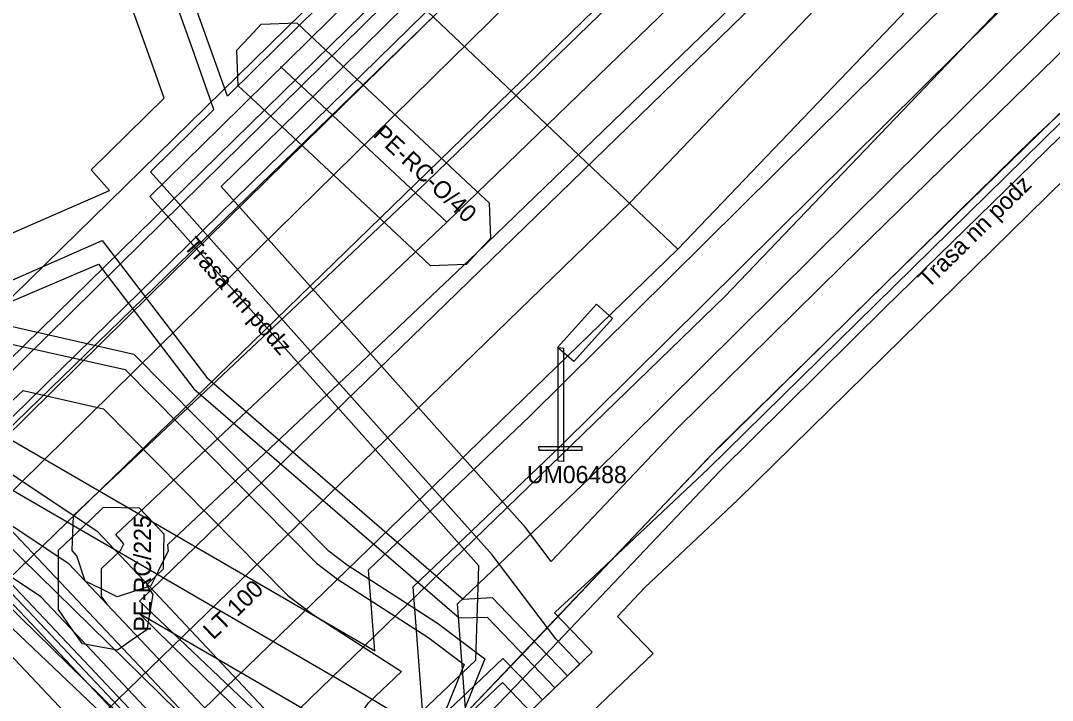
# Model space of a CAD drawing. Extents: x -762993 to -761845, y -975230 to -974501.
# Drawn here: x -762256.7 to -762232.71, y -974983.83 to -974968.01 of the extents above; entities that cross this region are included whole.
import ezdxf

# ---------------------------------------------------------------- set-up
doc = ezdxf.new("R2010")
doc.units = 0
for name, color, linetype in [('IS_CETIN_chranicka', 7, 'Continuous'), ('IS_CETIN_OP', 7, 'Continuous'), ('IS_CETIN_podzem metalika zam', 7, 'Continuous'), ('IS_CETIN_podzem optika zam', 7, 'Continuous'), ('IS_CEZ-D_anotace', 7, 'Continuous'), ('IS_CEZ-D_el vedeni NN podzem', 7, 'Continuous'), ('IS_CEZ-D_el vedeni VN podzem', 7, 'Continuous'), ('IS_CEZ-D_el vedeni VN podzem soubeh investice', 7, 'Continuous'), ('IS_CEZ-D_OP', 7, 'Continuous'), ('IS_CEZ-T_parovod', 7, 'Continuous'), ('IS_CEZ-T_parovod OP', 7, 'Continuous'), ('IS_DPmUL_OP', 7, 'Continuous'), ('IS_DPmUL_trakce vedeni', 7, 'Continuous'), ('IS_DPmUL_VO lampy', 7, 'Continuous'), ('IS_DPmUL_VO lampy anotace', 7, 'Continuous'), ('IS_DPmUL_VO vedeni podzem', 7, 'Continuous'), ('IS_GASNET_plyn NTL anotace', 7, 'Continuous'), ('IS_GASNET_plyn NTL pripojky', 7, 'Continuous'), ('IS_GASNET_plyn NTL rad', 7, 'Continuous'), ('IS_GASNET_plyn OP', 7, 'Continuous'), ('IS_SCVK_vodovod anotace', 7, 'Continuous'), ('IS_SCVK_vodovod OP', 7, 'Continuous'), ('IS_SCVK_vodovod pripojky', 7, 'Continuous'), ('IS_SCVK_vodovod privadec', 7, 'Continuous'), ('IS_T-Mobile_OP', 7, 'Continuous'), ('IS_T-Mobile_podzem optika', 7, 'Continuous'), ('IS_TPS_podzem metalika', 7, 'Continuous')]:
    doc.layers.add(name, color=color, linetype=linetype)

msp = doc.modelspace()

# ---------------------------------------------------------------- linework, layer by layer
at = {"layer": 'IS_CETIN_chranicka'}
for points in [[(-762258.261, -974979.697), (-762251.681, -974986.657)], [(-762258.479, -974979.903), (-762251.899, -974986.863)]]:
    msp.add_lwpolyline(points, dxfattribs=at)
at = {"layer": 'IS_CETIN_OP'}
for p, q in [((-762254.387, -974973.681), (-762261.009, -974980.205)), ((-762252.983, -974975.105), (-762257.358, -974979.415))]:
    msp.add_line(p, q, dxfattribs=at)
for points in [[(-762224.35, -974947.167), (-762239.502, -974961.816), (-762240.717, -974963.012), (-762243.097, -974965.371), (-762252.983, -974975.106)], [(-762241.648, -974961.122), (-762242.123, -974961.588), (-762244.503, -974963.949), (-762254.387, -974973.68)], [(-762281.558, -974973.1), (-762274.643, -974973.209), (-762271.979, -974979.65), (-762261.259, -974982.679), (-762258.547, -974981.068), (-762252.538, -974987.424), (-762250.848, -974989.451)], [(-762257.358, -974979.415), (-762251.042, -974986.096), (-762249.989, -974987.358)]]:
    msp.add_lwpolyline(points, dxfattribs=at)
at = {"layer": 'IS_CETIN_podzem metalika zam'}
for points in [[(-762225.045, -974946.448), (-762240.2, -974961.1), (-762241.42, -974962.3), (-762243.8, -974964.66), (-762253.685, -974974.393)], [(-762253.685, -974974.393), (-762258.26, -974978.9)]]:
    msp.add_lwpolyline(points, dxfattribs=at)
at = {"layer": 'IS_CETIN_podzem optika zam'}
msp.add_lwpolyline([(-762282.79, -974972.08), (-762273.97, -974972.22), (-762271.24, -974978.82), (-762261.4, -974981.6), (-762258.37, -974979.8), (-762251.79, -974986.76), (-762250.08, -974988.81)], dxfattribs=at)
at = {"layer": 'IS_CEZ-D_el vedeni NN podzem'}
for points in [[(-762247.847, -974984.536), (-762246.114, -974982.893), (-762246.05, -974980.697), (-762253.7, -974972.107), (-762252.057, -974970.493), (-762250.973, -974969.428), (-762239.791, -974958.41), (-762235.916, -974954.845), (-762234.541, -974953.31), (-762221.186, -974940.477), (-762220.991, -974940.306), (-762216.22, -974936.128), (-762203.456, -974923.483), (-762203.186, -974923.213), (-762202.673, -974922.708), (-762197.126, -974917.211), (-762182.367, -974902.622)], [(-762292.054, -974954.011), (-762292.145, -974953.937), (-762291.358, -974953.166), (-762290.951, -974953.062), (-762289.257, -974952.627), (-762288.969, -974952.553), (-762288.196, -974955.224), (-762285.856, -974966.323), (-762272.266, -974963.899), (-762272.118, -974964.474), (-762271.031, -974969.629), (-762269.385, -974976.005), (-762268.341, -974977.635), (-762265.074, -974979.234), (-762262.734, -974979.395), (-762260.132, -974977.413), (-762257.177, -974974.654), (-762254.887, -974973.678), (-762252.67, -974976.58), (-762246.502, -974981.906), (-762245.853, -974981.888), (-762245.113, -974982.66), (-762244.276, -974983.534), (-762244.131, -974983.395)], [(-762234.834, -974953.037), (-762236.201, -974954.564), (-762240.067, -974958.12), (-762251.254, -974969.143), (-762251.891, -974969.769), (-762252.332, -974968.535), (-762253.876, -974964.216), (-762253.878, -974964.21), (-762254.236, -974964.12), (-762254.284, -974964.314)], [(-762272.945, -974957.326), (-762271.974, -974963.424), (-762270.341, -974970.221), (-762269.011, -974975.847), (-762268.064, -974977.325), (-762264.969, -974978.841), (-762262.749, -974978.993), (-762260.312, -974977.034), (-762257.295, -974974.217), (-762254.804, -974973.128), (-762252.371, -974976.312), (-762246.411, -974981.474), (-762245.736, -974981.431), (-762244.85, -974982.356), (-762243.987, -974983.257), (-762244.131, -974983.395)], [(-762244.131, -974983.395), (-762243.698, -974982.98), (-762244.256, -974982.397), (-762245.738, -974980.442), (-762253.68, -974971.528), (-762252.205, -974970.078), (-762252.708, -974968.669), (-762254.179, -974964.552), (-762254.181, -974964.546), (-762254.333, -974964.508), (-762254.284, -974964.314)], [(-762223.572, -974968.926), (-762223.717, -974969.063), (-762224.197, -974968.555), (-762227.309, -974965.261), (-762240.713, -974978.438), (-762243.49, -974981.054), (-762244.149, -974981.659), (-762244.288, -974981.787), (-762243.667, -974982.434), (-762243.409, -974982.703), (-762244.131, -974983.395)], [(-762193.524, -974995.955), (-762196.315, -974995.713), (-762196.321, -974995.763), (-762206.82, -974995.223), (-762221.661, -974993.755), (-762245.947, -974992.564), (-762248.224, -974989.473), (-762248.642, -974987.043), (-762248.543, -974986.191), (-762247.498, -974984.757), (-762245.839, -974983.184), (-762245.485, -974982.848), (-762245.111, -974983.239), (-762244.564, -974983.81), (-762244.131, -974983.395)], [(-762193.524, -974995.955), (-762196.714, -974995.678), (-762196.674, -974995.344), (-762206.79, -974994.824), (-762221.625, -974993.357), (-762245.684, -974992.246), (-762247.846, -974989.312), (-762248.238, -974987.032), (-762248.152, -974986.29), (-762247.149, -974984.977), (-762245.644, -974983.55), (-762245.499, -974983.413), (-762245.127, -974983.801), (-762244.853, -974984.087), (-762244.131, -974983.395)]]:
    msp.add_lwpolyline(points, dxfattribs=at)
at = {"layer": 'IS_CEZ-D_el vedeni VN podzem'}
for points in [[(-762178.94, -974917.38), (-762180.88, -974919.33), (-762183.85, -974922.18), (-762189.02, -974927.27), (-762191.6, -974929.28), (-762204.29, -974941.85), (-762215.61, -974952.68), (-762222.04, -974959.06), (-762225.71, -974962.96), (-762226.91, -974964.67), (-762236.89, -974974.42), (-762240.73, -974978.21), (-762245.09, -974982.81)], [(-762269.579, -974969.967), (-762269.216, -974971.463), (-762268.263, -974975.531), (-762267.512, -974976.705), (-762264.757, -974978.053), (-762262.777, -974978.189), (-762259.951, -974977.791), (-762257.059, -974975.091), (-762254.069, -974975.768), (-762249.558, -974980.329), (-762249.105, -974980.676), (-762247.006, -974982.026), (-762245.904, -974982.859), (-762247.37, -974986.49), (-762247.43, -974987.01), (-762247.09, -974988.99), (-762245.16, -974991.61), (-762241.64, -974993.28), (-762221.77, -974994.95), (-762206.91, -974996.42), (-762195.262, -974997.018), (-762195.119, -974995.819), (-762194.458, -974994.436)], [(-762269.605, -974971.556), (-762268.637, -974975.689), (-762267.788, -974977.015), (-762264.863, -974978.447), (-762262.763, -974978.591), (-762259.77, -974978.169), (-762256.941, -974975.528), (-762254.271, -974976.132), (-762249.823, -974980.63), (-762249.335, -974981.004), (-762247.235, -974982.354), (-762246.39, -974982.993), (-762247.761, -974986.39), (-762247.834, -974987.021), (-762247.468, -974989.151), (-762245.422, -974991.928), (-762241.746, -974993.673), (-762221.806, -974995.348), (-762206.94, -974996.819), (-762194.909, -974997.437), (-762194.72, -974995.856), (-762194.458, -974994.436)], [(-762245.09, -974982.81), (-762246.99, -974984.79), (-762247.4, -974985.77), (-762247.54, -974987.01), (-762247.5, -974988.33), (-762246.71, -974990.37), (-762245.42, -974991.69), (-762241.81, -974993.76), (-762241.12, -974993.94), (-762236.96, -974994.44), (-762231.73, -974994.71), (-762227.11, -974994.8), (-762224.15, -974995.55), (-762219.32, -974995.76), (-762207.1, -974996.91), (-762200.67, -974997.34), (-762199.56, -974997.3), (-762198.56, -974996.73), (-762198.04, -974995.71)]]:
    msp.add_lwpolyline(points, dxfattribs=at)
at = {"layer": 'IS_CEZ-D_el vedeni VN podzem soubeh investice'}
msp.add_lwpolyline([(-762246.655, -974985.018), (-762244.801, -974983.086), (-762240.444, -974978.49), (-762236.61, -974974.705), (-762226.604, -974964.93), (-762225.399, -974963.213), (-762221.753, -974959.339), (-762215.331, -974952.967), (-762204.011, -974942.137), (-762191.335, -974929.581), (-762188.756, -974927.571), (-762183.571, -974922.467), (-762180.6, -974919.615), (-762178.658, -974917.664), (-762169.2, -974908.366)], dxfattribs=at)
at = {"layer": 'IS_CEZ-D_OP'}
msp.add_line((-762242.183, -974981.196), (-762242.822, -974981.871), dxfattribs=at)
for points in [[(-762252.034, -974971.872), (-762251.356, -974971.206), (-762250.272, -974970.141), (-762239.101, -974959.134), (-762235.203, -974955.548), (-762233.821, -974954.005), (-762220.51, -974941.214), (-762220.332, -974941.058), (-762215.538, -974936.86), (-762202.751, -974924.192), (-762202.482, -974923.923), (-762201.97, -974923.419), (-762196.423, -974917.922), (-762181.665, -974903.334)], [(-762224.65, -974960.374), (-762226.487, -974962.327), (-762227.675, -974964.02), (-762237.591, -974973.706), (-762241.444, -974977.51), (-762244.368, -974980.594)], [(-762254.633, -974971.962), (-762255.06, -974971.482), (-762253.362, -974969.813), (-762253.65, -974969.005), (-762254.943, -974965.386), (-762255.548, -974965.235), (-762254.96, -974962.907)], [(-762222.885, -974969.653), (-762223.757, -974970.477), (-762224.924, -974969.242), (-762227.335, -974966.689), (-762240.02, -974979.159), (-762242.183, -974981.196)], [(-762244.368, -974980.594), (-762244.965, -974979.806), (-762252.034, -974971.872)], [(-762261.942, -974977.062), (-762260.967, -974976.278), (-762257.852, -974973.369), (-762254.633, -974971.962)], [(-762261.034, -974979.357), (-762259.318, -974979.115), (-762256.645, -974976.62), (-762254.777, -974977.043), (-762250.486, -974981.382), (-762249.911, -974981.823), (-762247.842, -974983.153)], [(-762242.822, -974981.871), (-762241.995, -974982.733), (-762244.883, -974985.501)], [(-762243.344, -974994.033), (-762246.733, -974993.857), (-762249.549, -974990.037), (-762250.056, -974987.081), (-762249.898, -974985.725), (-762248.609, -974983.88), (-762247.842, -974983.153)]]:
    msp.add_lwpolyline(points, dxfattribs=at)
at = {"layer": 'IS_CEZ-T_parovod'}
msp.add_lwpolyline([(-762252.5, -975008.59), (-762252.58, -975007.19), (-762253.19, -974987.18), (-762253.2, -974985.67), (-762257.54, -974981.54), (-762246.7, -974971.01), (-762237.24, -974961.81), (-762238.76, -974960.21), (-762237.06, -974958.42), (-762235.35, -974960.05), (-762220.52, -974945.72), (-762219.73, -974944.77), (-762200.92, -974926.55), (-762198.18, -974929.41), (-762193.38, -974924.68)], dxfattribs=at)
at = {"layer": 'IS_CEZ-T_parovod OP'}
for points in [[(-762254.996, -975008.733), (-762255.078, -975007.299), (-762255.69, -974987.226), (-762255.693, -974986.749), (-762261.147, -974981.559), (-762248.442, -974969.217), (-762240.754, -974961.74), (-762242.208, -974960.21), (-762237.148, -974954.882), (-762235.362, -974956.585), (-762222.355, -974944.017), (-762221.566, -974943.068), (-762200.854, -974923.005), (-762198.129, -974925.85), (-762195.116, -974922.881)], [(-762250.004, -975008.447), (-762250.082, -975007.081), (-762250.69, -974987.134), (-762250.707, -974984.591), (-762253.933, -974981.521), (-762244.958, -974972.803), (-762235.373, -974963.482), (-762235.338, -974963.515), (-762218.685, -974947.423), (-762217.894, -974946.472), (-762200.986, -974930.095), (-762198.231, -974932.97), (-762193.371, -974928.181)]]:
    msp.add_lwpolyline(points, dxfattribs=at)
at = {"layer": 'IS_DPmUL_OP'}
for p, q in [((-762244.874, -974977.229), (-762228.861, -974961.348)), ((-762243.466, -974978.649), (-762227.465, -974962.78))]:
    msp.add_line(p, q, dxfattribs=at)
for points in [[(-762248.464, -974982.682), (-762248.632, -974982.582), (-762257.925, -974977.187), (-762258.333, -974977.451)], [(-762248.464, -974982.682), (-762248.608, -974980.785), (-762244.86, -974977.215)], [(-762250.756, -974991.837), (-762245.807, -974991.227), (-762246.542, -974981.579), (-762243.48, -974978.663)], [(-762246.438, -974993.901), (-762252.18, -974986.336), (-762258.617, -974980.029), (-762258.624, -974980.021)], [(-762248.56, -974987.797), (-762250.676, -974985.01), (-762253.935, -974981.816)], [(-762248.56, -974987.797), (-762248.807, -974984.805), (-762249.646, -974984.306), (-762253.935, -974981.816)]]:
    msp.add_lwpolyline(points, dxfattribs=at)
at = {"layer": 'IS_DPmUL_trakce vedeni'}
msp.add_lwpolyline([(-762245.348, -974993.683), (-762251.428, -974985.673), (-762257.908, -974979.323), (-762259.308, -974977.883), (-762264.868, -974978.223), (-762267.558, -974978.313), (-762268.458, -974976.203), (-762270.168, -974970.153), (-762271.628, -974963.603), (-762274.118, -974952.573), (-762276.178, -974943.173), (-762279.078, -974930.913), (-762281.258, -974920.463), (-762282.448, -974915.363), (-762282.938, -974913.343), (-762283.168, -974912.233), (-762284.728, -974904.823), (-762285.898, -974900.343), (-762287.198, -974894.413), (-762288.448, -974888.003), (-762289.278, -974884.593), (-762294.708, -974861.303), (-762294.911, -974860.32)], dxfattribs=at)
at = {"layer": 'IS_DPmUL_VO lampy'}
for points in [[(-762243.31, -974974.609), (-762242.94, -974974.939), (-762243.84, -974975.939), (-762244.22, -974975.619)], [(-762244.2, -974975.619), (-762244.08, -974975.629), (-762244.08, -974978.269), (-762244.2, -974978.259)], [(-762244.65, -974977.919), (-762243.65, -974977.919), (-762243.65, -974978.009), (-762244.64, -974978.009)]]:
    msp.add_lwpolyline(points, close=True, dxfattribs=at)
at = {"layer": 'IS_DPmUL_VO vedeni podzem'}
for points in [[(-762244.17, -974977.939), (-762228.163, -974962.064)], [(-762250.879, -974990.845), (-762246.877, -974990.351), (-762247.575, -974981.182), (-762244.17, -974977.939)], [(-762250.879, -974990.845), (-762247.363, -974990.15), (-762247.853, -974984.209), (-762249.139, -974983.444), (-762257.897, -974978.36), (-762260.929, -974980.32), (-762264.695, -974981.086), (-762267.897, -974979.732)]]:
    msp.add_lwpolyline(points, dxfattribs=at)
at = {"layer": 'IS_GASNET_plyn NTL pripojky'}
msp.add_lwpolyline([(-762246.79, -974972.7), (-762250.66, -974969.08)], dxfattribs=at)
at = {"layer": 'IS_GASNET_plyn NTL rad'}
for points in [[(-762254.38, -974980.34), (-762254.3, -974980.18), (-762254.49, -974979.97), (-762249.33, -974975.11), (-762246.79, -974972.7), (-762240.45, -974966.56), (-762232.17, -974958.5), (-762223.94, -974950.53), (-762218.08, -974944.94), (-762212.07, -974939.13), (-762200.83, -974928.57), (-762199.24, -974927.03), (-762198.4, -974925.79), (-762191.542, -974918.748)], [(-762235.16, -974995.41), (-762241.303, -974994.697), (-762241.895, -974994.628), (-762245.49, -974994.21), (-762251.83, -974984.63), (-762254.68, -974981.6), (-762255.58, -974980.65), (-762257.13, -974979.62), (-762258.52, -974978.68), (-762260.62, -974979.38), (-762261.995, -974979.661), (-762262.553, -974979.775), (-762262.92, -974979.85), (-762265.56, -974979.89), (-762268.53, -974977.47), (-762279.25, -974979.81)], [(-762254.68, -974981.6), (-762254.82, -974981.4), (-762254.82, -974980.76), (-762254.38, -974980.34)]]:
    msp.add_lwpolyline(points, dxfattribs=at)
at = {"layer": 'IS_GASNET_plyn OP'}
for points in [[(-762231.473, -974959.217), (-762239.753, -974967.277), (-762246.098, -974973.422), (-762248.643, -974975.837), (-762253.287, -974980.211), (-762253.268, -974980.351), (-762253.406, -974980.627), (-762253.486, -974980.787), (-762253.671, -974981.158), (-762254.457, -974981.42), (-762254.827, -974981.234), (-762255.198, -974981.049), (-762255.394, -974980.462), (-762255.506, -974980.338), (-762255.473, -974979.522), (-762255.176, -974979.242), (-762250.017, -974974.383), (-762247.482, -974971.978), (-762241.147, -974965.843), (-762232.867, -974957.783), (-762224.633, -974949.809)], [(-762279.483, -974978.837), (-762268.743, -974976.493), (-762268.52, -974976.444), (-762268.075, -974976.55), (-762267.898, -974976.695), (-762265.211, -974978.885), (-762263.029, -974978.852), (-762262.753, -974978.795), (-762262.195, -974978.681), (-762260.879, -974978.412), (-762258.836, -974977.731), (-762258.615, -974977.657), (-762258.153, -974977.721), (-762257.96, -974977.852), (-762256.573, -974978.789), (-762254.932, -974979.88), (-762253.953, -974980.914), (-762251.043, -974984.007)], [(-762252.617, -974985.253), (-762255.407, -974982.286), (-762256.228, -974981.42), (-762257.687, -974980.451), (-762258.672, -974979.785), (-762260.361, -974980.348), (-762261.795, -974980.641), (-762262.353, -974980.755), (-762262.811, -974980.848), (-762265.909, -974980.895), (-762268.788, -974978.55), (-762279.017, -974980.783)]]:
    msp.add_lwpolyline(points, dxfattribs=at)
for points in [[(-762247.171, -974973.713), (-762247.473, -974973.43), (-762251.343, -974969.81), (-762251.645, -974969.527), (-762251.673, -974968.699), (-762251.39, -974968.397), (-762251.107, -974968.095), (-762250.279, -974968.067), (-762249.977, -974968.35), (-762246.107, -974971.97), (-762245.805, -974972.253), (-762245.777, -974973.081), (-762246.06, -974973.383), (-762246.343, -974973.685)], [(-762253.69, -974981.063), (-762253.777, -974981.147), (-762253.623, -974981.366), (-762253.767, -974982.182), (-762254.107, -974982.419), (-762254.446, -974982.657), (-762255.262, -974982.513), (-762255.499, -974982.173), (-762255.82, -974981.715), (-762255.82, -974980.332), (-762255.07, -974979.617), (-762254.771, -974979.331), (-762253.943, -974979.35), (-762253.657, -974979.65), (-762253.371, -974979.949), (-762253.39, -974980.777)]]:
    msp.add_lwpolyline(points, close=True, dxfattribs=at)
at = {"layer": 'IS_SCVK_vodovod OP'}
for points in [[(-762217.473, -974947.113), (-762218.81, -974948.43), (-762220.343, -974950.02), (-762232.223, -974961.467), (-762242.519, -974972.237), (-762258.353, -974987.594)], [(-762215.297, -974949.321), (-762216.606, -974950.61), (-762218.151, -974952.212), (-762230.027, -974963.655), (-762240.319, -974974.421), (-762256.335, -974989.956)]]:
    msp.add_lwpolyline(points, dxfattribs=at)
at = {"layer": 'IS_SCVK_vodovod pripojky'}
msp.add_lwpolyline([(-762241.419, -974973.329), (-762248.308, -974966.779)], dxfattribs=at)
at = {"layer": 'IS_SCVK_vodovod privadec'}
msp.add_lwpolyline([(-762216.385, -974948.217), (-762217.708, -974949.52), (-762219.247, -974951.116), (-762231.125, -974962.561), (-762241.419, -974973.329), (-762257.344, -974988.775)], dxfattribs=at)
at = {"layer": 'IS_T-Mobile_OP'}
for p, q in [((-762259.72, -974977.2), (-762246.058, -974963.818)), ((-762258.76, -974979.06), (-762243.92, -974964.524))]:
    msp.add_line(p, q, dxfattribs=at)
at = {"layer": 'IS_T-Mobile_podzem optika'}
msp.add_lwpolyline([(-762259.24, -974978.13), (-762244.62, -974963.81)], dxfattribs=at)
msp.add_lwpolyline([(-762259.24, -974978.13), (-762244.62, -974963.81)], dxfattribs=at)
at = {"layer": 'IS_TPS_podzem metalika'}
msp.add_lwpolyline([(-762172.29, -974910.28), (-762185.23, -974922.87), (-762190.46, -974927.24), (-762198, -974934.74), (-762201.39, -974938.15), (-762206.9, -974943.61), (-762214.43, -974950.91), (-762220.21, -974956.46), (-762222.55, -974958.76), (-762223.79, -974960.27), (-762224.33, -974962.55), (-762233.162, -974970.759), (-762240.486, -974977.956), (-762246.238, -974984.004)], dxfattribs=at)

# ---------------------------------------------------------------- texts
at = {"layer": 'IS_CEZ-D_anotace'}
for rotation, p in [(44.5107, (-762235.6, -974974.253)), (311.6997, (-762252.93, -974973.272))]:
    msp.add_text('Trasa nn podz', height=0.4, rotation=rotation, dxfattribs=at).set_placement(p)
at = {"layer": 'IS_DPmUL_VO lampy anotace'}
msp.add_text('UM06488', height=0.4, dxfattribs=at).set_placement((-762244.926, -974978.772))
at = {"layer": 'IS_GASNET_plyn NTL anotace'}
for s, rotation, p in [('PE-RC-O/40', 316.9117, (-762248.525, -974970.69)), ('PE-RC/225', 90, (-762253.669, -974982.225))]:
    msp.add_text(s, height=0.4, rotation=rotation, dxfattribs=at).set_placement(p)
at = {"layer": 'IS_SCVK_vodovod anotace'}
msp.add_text('LT 100', height=0.4, rotation=44, dxfattribs=at).set_placement((-762252.221, -974982.433))

doc.saveas('drawing.dxf')
